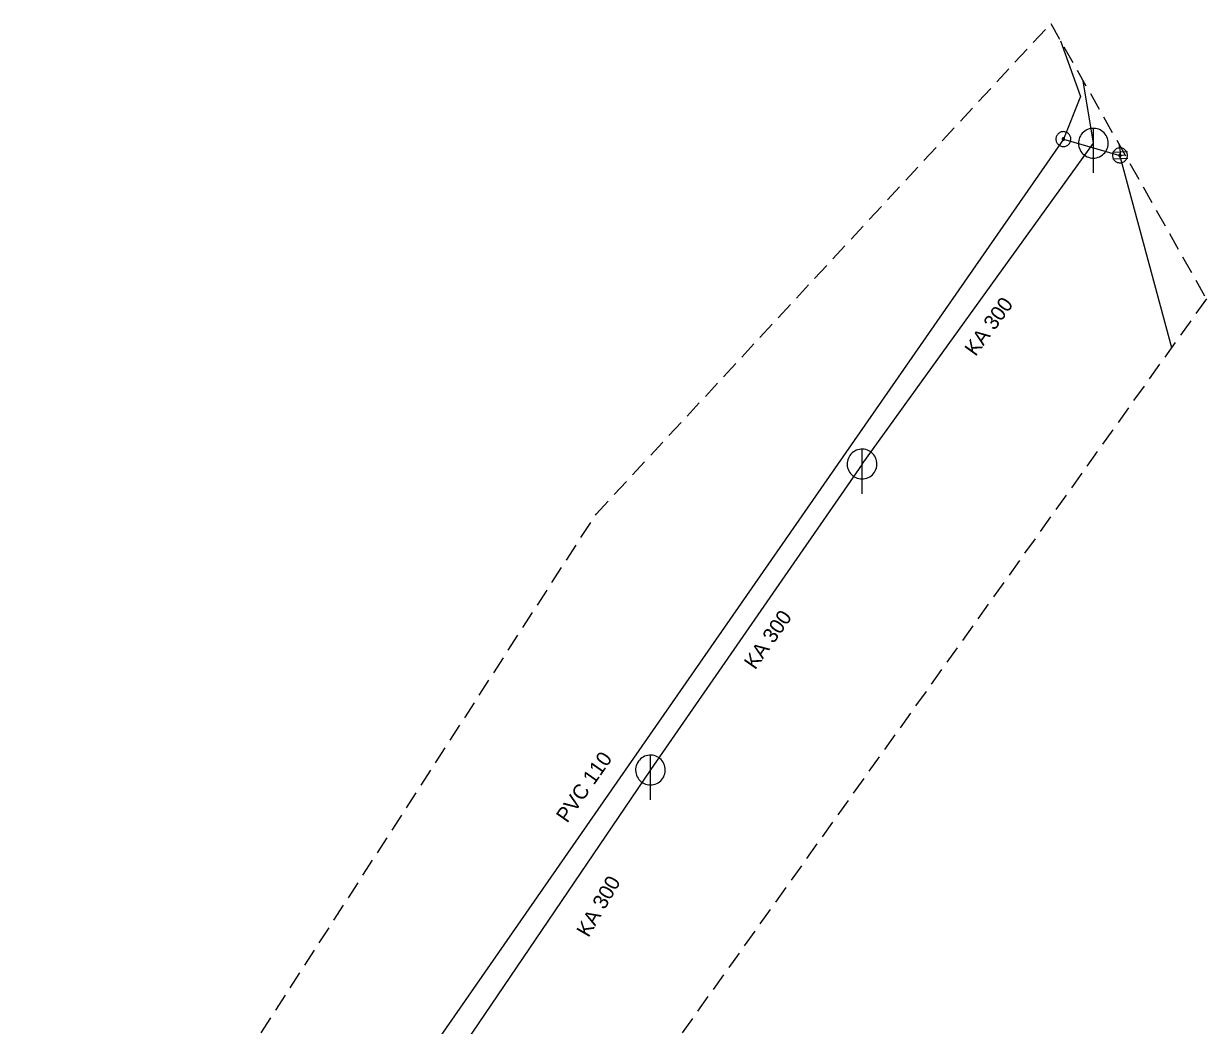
# Model space of a CAD drawing. Extents: x -686636 to -686482, y -972667 to -972167.
# Drawn here: x -686561.5 to -686482.1, y -972234.6 to -972167.3 of the extents above; entities that cross this region are included whole.
import ezdxf

# ---------------------------------------------------------------- set-up
doc = ezdxf.new("R2010")
doc.units = 0
doc.header["$LTSCALE"] = 0.4
doc.linetypes.add('MEDIUM_DASHED', pattern=[4.5, 3, -1.5])
for name, color, linetype, lineweight in [('1', 7, 'MEDIUM_DASHED', 25), ('14', 7, 'Continuous', 25), ('17', 7, 'Continuous', 25), ('22', 7, 'Continuous', 13), ('34', 7, 'Continuous', 13), ('47', 7, 'Continuous', 13)]:
    doc.layers.add(name, color=color, linetype=linetype, lineweight=lineweight)

msp = doc.modelspace()

# ---------------------------------------------------------------- linework, layer by layer
at = {"layer": '1'}
msp.add_lwpolyline([(-686523.086, -972200.227), (-686492.539, -972167.269), (-686482.089, -972185.758), (-686542.379, -972270.164), (-686548.006, -972279.81), (-686543.183, -972295.084), (-686523.086, -972321.612), (-686521.478, -972360.197), (-686540.771, -972442.192), (-686521.478, -972473.543), (-686515.047, -972510.521), (-686519.067, -972578.85), (-686529.517, -972667.276), (-686549.614, -972665.668), (-686542.379, -972574.831), (-686589.003, -972562.773), (-686636.432, -972544.284), (-686625.981, -972525.795), (-686541.575, -972549.911), (-686539.967, -972501.678), (-686569.711, -972440.584), (-686549.614, -972329.65), (-686564.887, -972297.496), (-686572.926, -972277.399)], close=True, dxfattribs=at)
at = {"layer": '14'}
for p, q in [((-686489.68, -972175.3), (-686490.364, -972171.117)), ((-686505.219, -972196.85), (-686489.68, -972175.3)), ((-686505.219, -972196.85), (-686519.433, -972217.405)), ((-686519.433, -972217.405), (-686532.689, -972236.926))]:
    msp.add_line(p, q, dxfattribs=at)
at = {"layer": '14', "lineweight": 13}
for p, q in [((-686487.884, -972175.888), (-686487.892, -972176.119)), ((-686487.892, -972176.119), (-686487.564, -972176.071)), ((-686487.865, -972176.334), (-686487.892, -972176.119))]:
    msp.add_line(p, q, dxfattribs=at)
at = {"layer": '17'}
for p, q in [((-686491.693, -972175.023), (-686535.487, -972238.079)), ((-686491.693, -972175.023), (-686487.892, -972176.119)), ((-686487.973, -972175.347), (-686487.884, -972175.888)), ((-686487.865, -972176.334), (-686484.427, -972189.031))]:
    msp.add_line(p, q, dxfattribs=at)
msp.add_lwpolyline([(-686491.893, -972168.412), (-686490.548, -972172.168), (-686491.693, -972175.023)], dxfattribs=at)
at = {"layer": '22'}
for p, q in [((-686489.68, -972177.3), (-686489.679, -972174.3)), ((-686505.219, -972198.85), (-686505.218, -972195.85)), ((-686519.433, -972219.405), (-686519.432, -972216.405))]:
    msp.add_line(p, q, dxfattribs=at)
for points in [[(-686488.68, -972175.3), (-686488.685, -972175.191), (-686488.703, -972175.083), (-686488.733, -972174.977), (-686488.773, -972174.876), (-686488.825, -972174.779), (-686488.887, -972174.689), (-686488.959, -972174.606), (-686489.039, -972174.532), (-686489.127, -972174.466), (-686489.221, -972174.411), (-686489.321, -972174.366), (-686489.426, -972174.333), (-686489.533, -972174.311), (-686489.642, -972174.301), (-686489.752, -972174.303), (-686489.86, -972174.317), (-686489.967, -972174.342), (-686490.07, -972174.379), (-686490.168, -972174.428), (-686490.26, -972174.486), (-686490.346, -972174.555), (-686490.423, -972174.632), (-686490.492, -972174.718), (-686490.551, -972174.81), (-686490.599, -972174.908), (-686490.636, -972175.011), (-686490.662, -972175.118), (-686490.676, -972175.226), (-686490.679, -972175.336), (-686490.669, -972175.445), (-686490.648, -972175.552), (-686490.614, -972175.656), (-686490.57, -972175.756), (-686490.515, -972175.851), (-686490.449, -972175.939), (-686490.375, -972176.019), (-686490.292, -972176.091), (-686490.202, -972176.153), (-686490.106, -972176.205), (-686490.004, -972176.246), (-686489.899, -972176.276), (-686489.791, -972176.294), (-686489.681, -972176.3), (-686489.572, -972176.294), (-686489.464, -972176.276), (-686489.359, -972176.247), (-686489.257, -972176.206), (-686489.16, -972176.154), (-686489.07, -972176.092), (-686488.987, -972176.021), (-686488.912, -972175.941), (-686488.847, -972175.853), (-686488.791, -972175.759), (-686488.747, -972175.659), (-686488.713, -972175.555), (-686488.691, -972175.447), (-686488.681, -972175.338)], [(-686504.219, -972196.85), (-686504.224, -972196.741), (-686504.242, -972196.633), (-686504.272, -972196.527), (-686504.312, -972196.426), (-686504.364, -972196.329), (-686504.426, -972196.239), (-686504.498, -972196.156), (-686504.578, -972196.082), (-686504.666, -972196.016), (-686504.76, -972195.961), (-686504.86, -972195.916), (-686504.965, -972195.883), (-686505.072, -972195.861), (-686505.181, -972195.851), (-686505.291, -972195.853), (-686505.399, -972195.867), (-686505.506, -972195.892), (-686505.609, -972195.929), (-686505.707, -972195.978), (-686505.799, -972196.036), (-686505.885, -972196.105), (-686505.962, -972196.182), (-686506.031, -972196.268), (-686506.09, -972196.36), (-686506.138, -972196.458), (-686506.175, -972196.561), (-686506.201, -972196.668), (-686506.215, -972196.776), (-686506.218, -972196.886), (-686506.208, -972196.995), (-686506.187, -972197.102), (-686506.153, -972197.206), (-686506.109, -972197.306), (-686506.054, -972197.401), (-686505.988, -972197.489), (-686505.914, -972197.569), (-686505.831, -972197.641), (-686505.741, -972197.703), (-686505.645, -972197.755), (-686505.543, -972197.796), (-686505.438, -972197.826), (-686505.33, -972197.844), (-686505.22, -972197.85), (-686505.111, -972197.844), (-686505.003, -972197.826), (-686504.898, -972197.797), (-686504.796, -972197.756), (-686504.699, -972197.704), (-686504.609, -972197.642), (-686504.526, -972197.571), (-686504.451, -972197.491), (-686504.386, -972197.403), (-686504.33, -972197.309), (-686504.286, -972197.209), (-686504.252, -972197.105), (-686504.23, -972196.997), (-686504.22, -972196.888)], [(-686518.433, -972217.405), (-686518.438, -972217.296), (-686518.456, -972217.188), (-686518.486, -972217.082), (-686518.526, -972216.981), (-686518.578, -972216.884), (-686518.64, -972216.794), (-686518.712, -972216.711), (-686518.792, -972216.637), (-686518.88, -972216.571), (-686518.974, -972216.516), (-686519.074, -972216.471), (-686519.179, -972216.438), (-686519.286, -972216.416), (-686519.395, -972216.406), (-686519.505, -972216.408), (-686519.613, -972216.422), (-686519.72, -972216.447), (-686519.823, -972216.484), (-686519.921, -972216.533), (-686520.013, -972216.591), (-686520.099, -972216.66), (-686520.176, -972216.737), (-686520.245, -972216.823), (-686520.304, -972216.915), (-686520.352, -972217.013), (-686520.389, -972217.116), (-686520.415, -972217.223), (-686520.429, -972217.331), (-686520.432, -972217.441), (-686520.422, -972217.55), (-686520.401, -972217.657), (-686520.367, -972217.761), (-686520.323, -972217.861), (-686520.268, -972217.956), (-686520.202, -972218.044), (-686520.128, -972218.124), (-686520.045, -972218.196), (-686519.955, -972218.258), (-686519.859, -972218.31), (-686519.757, -972218.351), (-686519.652, -972218.381), (-686519.544, -972218.399), (-686519.434, -972218.405), (-686519.325, -972218.399), (-686519.217, -972218.381), (-686519.112, -972218.352), (-686519.01, -972218.311), (-686518.913, -972218.259), (-686518.823, -972218.197), (-686518.74, -972218.126), (-686518.665, -972218.046), (-686518.6, -972217.958), (-686518.544, -972217.864), (-686518.5, -972217.764), (-686518.466, -972217.66), (-686518.444, -972217.552), (-686518.434, -972217.443)]]:
    msp.add_lwpolyline(points, close=True, dxfattribs=at)
at = {"layer": '34'}
for p, q in [((-686488.383, -972175.913), (-686487.384, -972175.863)), ((-686488.364, -972176.359), (-686487.365, -972176.309))]:
    msp.add_line(p, q, dxfattribs=at)
at = {"layer": '47'}
for points in [[(-686491.587, -972174.534), (-686491.639, -972174.526), (-686491.691, -972174.523), (-686491.743, -972174.526), (-686491.795, -972174.533), (-686491.846, -972174.547), (-686491.895, -972174.566), (-686491.941, -972174.59), (-686491.985, -972174.618), (-686492.026, -972174.65), (-686492.063, -972174.687), (-686492.097, -972174.728), (-686492.125, -972174.772), (-686492.149, -972174.818), (-686492.167, -972174.867), (-686492.181, -972174.917), (-686492.189, -972174.969), (-686492.192, -972175.021), (-686492.189, -972175.074), (-686492.182, -972175.125), (-686492.168, -972175.176), (-686492.149, -972175.225), (-686492.126, -972175.272), (-686492.097, -972175.316), (-686492.065, -972175.357), (-686492.028, -972175.393), (-686491.987, -972175.427), (-686491.943, -972175.456), (-686491.897, -972175.479), (-686491.848, -972175.497), (-686491.798, -972175.511), (-686491.746, -972175.519), (-686491.694, -972175.522), (-686491.641, -972175.52), (-686491.59, -972175.512), (-686491.539, -972175.498), (-686491.49, -972175.48), (-686491.443, -972175.457), (-686491.399, -972175.428), (-686491.358, -972175.395), (-686491.322, -972175.358), (-686491.288, -972175.317), (-686491.26, -972175.274), (-686491.236, -972175.227), (-686491.218, -972175.178), (-686491.204, -972175.128), (-686491.196, -972175.076), (-686491.193, -972175.024), (-686491.195, -972174.972), (-686491.203, -972174.92), (-686491.217, -972174.869), (-686491.235, -972174.82), (-686491.259, -972174.774), (-686491.287, -972174.73), (-686491.32, -972174.689), (-686491.357, -972174.652), (-686491.398, -972174.618), (-686491.441, -972174.591), (-686491.488, -972174.566), (-686491.537, -972174.548)], [(-686491.675, -972174.942), (-686491.684, -972174.94), (-686491.692, -972174.941), (-686491.701, -972174.941), (-686491.709, -972174.942), (-686491.718, -972174.944), (-686491.726, -972174.948), (-686491.733, -972174.951), (-686491.741, -972174.956), (-686491.747, -972174.962), (-686491.753, -972174.968), (-686491.759, -972174.974), (-686491.764, -972174.982), (-686491.767, -972174.989), (-686491.771, -972174.996), (-686491.773, -972175.005), (-686491.775, -972175.014), (-686491.774, -972175.022), (-686491.774, -972175.031), (-686491.773, -972175.039), (-686491.771, -972175.048), (-686491.767, -972175.056), (-686491.764, -972175.063), (-686491.759, -972175.071), (-686491.754, -972175.078), (-686491.747, -972175.083), (-686491.741, -972175.089), (-686491.733, -972175.094), (-686491.726, -972175.097), (-686491.719, -972175.101), (-686491.71, -972175.103), (-686491.701, -972175.105), (-686491.693, -972175.104), (-686491.684, -972175.104), (-686491.676, -972175.103), (-686491.667, -972175.101), (-686491.66, -972175.098), (-686491.652, -972175.094), (-686491.644, -972175.089), (-686491.637, -972175.084), (-686491.632, -972175.077), (-686491.626, -972175.071), (-686491.621, -972175.063), (-686491.618, -972175.056), (-686491.614, -972175.049), (-686491.612, -972175.04), (-686491.61, -972175.031), (-686491.611, -972175.023), (-686491.611, -972175.014), (-686491.612, -972175.006), (-686491.614, -972174.997), (-686491.617, -972174.99), (-686491.621, -972174.982), (-686491.626, -972174.974), (-686491.632, -972174.968), (-686491.638, -972174.962), (-686491.644, -972174.956), (-686491.652, -972174.951), (-686491.659, -972174.948), (-686491.666, -972174.944)], [(-686487.786, -972175.63), (-686487.838, -972175.622), (-686487.89, -972175.619), (-686487.942, -972175.622), (-686487.994, -972175.629), (-686488.045, -972175.643), (-686488.094, -972175.662), (-686488.14, -972175.686), (-686488.184, -972175.714), (-686488.225, -972175.746), (-686488.262, -972175.783), (-686488.296, -972175.824), (-686488.324, -972175.868), (-686488.348, -972175.914), (-686488.366, -972175.963), (-686488.38, -972176.013), (-686488.388, -972176.065), (-686488.391, -972176.117), (-686488.388, -972176.17), (-686488.381, -972176.221), (-686488.367, -972176.272), (-686488.348, -972176.321), (-686488.325, -972176.368), (-686488.296, -972176.412), (-686488.264, -972176.453), (-686488.227, -972176.489), (-686488.186, -972176.523), (-686488.142, -972176.552), (-686488.096, -972176.575), (-686488.047, -972176.593), (-686487.997, -972176.607), (-686487.945, -972176.615), (-686487.893, -972176.618), (-686487.84, -972176.616), (-686487.789, -972176.608), (-686487.738, -972176.594), (-686487.689, -972176.576), (-686487.642, -972176.553), (-686487.598, -972176.524), (-686487.557, -972176.491), (-686487.521, -972176.454), (-686487.487, -972176.413), (-686487.459, -972176.37), (-686487.435, -972176.323), (-686487.417, -972176.274), (-686487.403, -972176.224), (-686487.395, -972176.172), (-686487.392, -972176.12), (-686487.394, -972176.068), (-686487.402, -972176.016), (-686487.416, -972175.965), (-686487.434, -972175.916), (-686487.458, -972175.87), (-686487.486, -972175.826), (-686487.519, -972175.785), (-686487.556, -972175.748), (-686487.597, -972175.714), (-686487.64, -972175.687), (-686487.687, -972175.662), (-686487.736, -972175.644)], [(-686487.874, -972176.038), (-686487.883, -972176.036), (-686487.891, -972176.037), (-686487.9, -972176.037), (-686487.908, -972176.038), (-686487.917, -972176.04), (-686487.925, -972176.044), (-686487.932, -972176.047), (-686487.94, -972176.052), (-686487.946, -972176.058), (-686487.952, -972176.064), (-686487.958, -972176.07), (-686487.963, -972176.078), (-686487.966, -972176.085), (-686487.97, -972176.092), (-686487.972, -972176.101), (-686487.974, -972176.11), (-686487.973, -972176.118), (-686487.973, -972176.127), (-686487.972, -972176.135), (-686487.97, -972176.144), (-686487.966, -972176.152), (-686487.963, -972176.159), (-686487.958, -972176.167), (-686487.953, -972176.174), (-686487.946, -972176.179), (-686487.94, -972176.185), (-686487.932, -972176.19), (-686487.925, -972176.193), (-686487.918, -972176.197), (-686487.909, -972176.199), (-686487.9, -972176.201), (-686487.892, -972176.2), (-686487.883, -972176.2), (-686487.875, -972176.199), (-686487.866, -972176.197), (-686487.859, -972176.194), (-686487.851, -972176.19), (-686487.843, -972176.185), (-686487.836, -972176.18), (-686487.831, -972176.173), (-686487.825, -972176.167), (-686487.82, -972176.159), (-686487.817, -972176.152), (-686487.813, -972176.145), (-686487.811, -972176.136), (-686487.809, -972176.127), (-686487.81, -972176.119), (-686487.81, -972176.11), (-686487.811, -972176.102), (-686487.813, -972176.093), (-686487.816, -972176.086), (-686487.82, -972176.078), (-686487.825, -972176.07), (-686487.831, -972176.064), (-686487.837, -972176.058), (-686487.843, -972176.052), (-686487.851, -972176.047), (-686487.858, -972176.044), (-686487.865, -972176.04)]]:
    msp.add_lwpolyline(points, close=True, dxfattribs=at)

# ---------------------------------------------------------------- texts
at = {"layer": '1'}
for s, rotation, p in [('KA 300', 54, (-686497.594, -972189.668)), ('KA 300', 55, (-686512.398, -972210.723)), ('PVC 110 ', 55, (-686525.023, -972221.019)), ('KA 300', 60, (-686523.597, -972228.703))]:
    msp.add_text(s, height=1, rotation=rotation, dxfattribs=at).set_placement(p)

doc.saveas('drawing.dxf')
